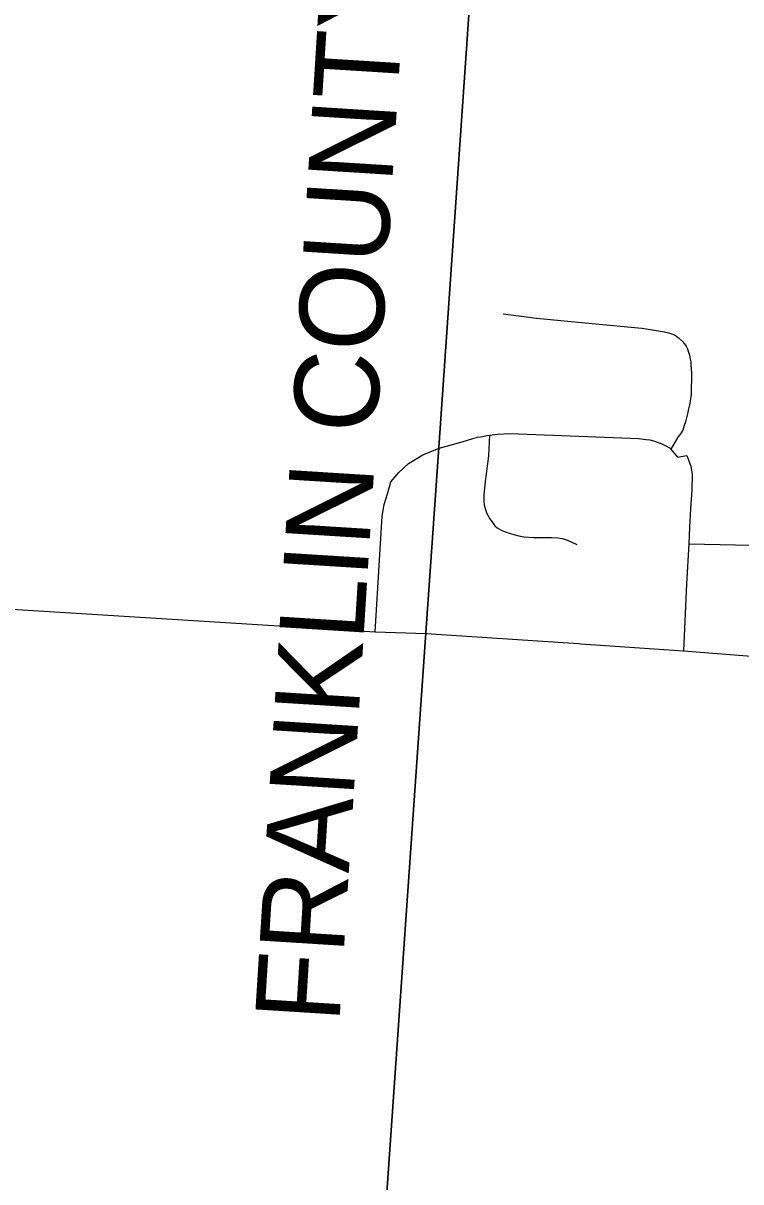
# Model space of a CAD drawing. Extents: x 1880545 to 1948545, y 79309 to 723051.
# Drawn here: x 1887669 to 1890853, y 706837 to 711978 of the extents above; entities that cross this region are included whole.
import ezdxf

# ---------------------------------------------------------------- set-up
doc = ezdxf.new("R2010")
doc.units = 0
for name, color, linetype in [('GM_X_City_Street', 7, 'Continuous'), ('GM_X_County', 7, 'Continuous'), ('GM_X_County_Text', 7, 'Continuous'), ('GM_X_Township', 7, 'Continuous'), ('GM_X_Township_Road', 7, 'Continuous')]:
    doc.layers.add(name, color=color, linetype=linetype)

msp = doc.modelspace()

# ---------------------------------------------------------------- linework, layer by layer
at = {"layer": 'GM_X_City_Street'}
msp.add_line((1890622.3, 709667), (1891097.2, 709657.6), dxfattribs=at)
for points in [[(1889799, 710687.4), (1889946.7, 710668.7), (1890194.3, 710645.5), (1890414, 710624.4), (1890469.9, 710616.2), (1890513.8, 710607.9), (1890533.8, 710603.8), (1890545.8, 710599.8), (1890561.7, 710593.7), (1890577.6, 710581.6), (1890593.6, 710567.4), (1890603.5, 710555.4), (1890611.4, 710545.3), (1890617.3, 710533.3), (1890619.3, 710523.2), (1890625.2, 710505.1), (1890629.1, 710487.1), (1890631.1, 710475.1), (1890631, 710461), (1890634.8, 710426.9), (1890632.4, 710330.6), (1890628.2, 710300.6), (1890626.2, 710284.5), (1890620, 710260.5), (1890618, 710250.5), (1890615.9, 710238.5), (1890607.8, 710208.5), (1890601.7, 710192.4), (1890595.7, 710172.4), (1890585.6, 710156.4), (1890573.5, 710140.4), (1890543, 710088.1)], [(1889514.4, 710091.8), (1889616.4, 710120.7), (1889664.5, 710134.6), (1889684.5, 710140.5), (1889708.5, 710144.4), (1889726.4, 710148.3), (1889739, 710149.8), (1889774.4, 710154.1), (1889828.4, 710157.9), (1890325.8, 710137.6), (1890399.7, 710135.2), (1890433.6, 710131), (1890449.6, 710129), (1890465.5, 710124.9), (1890499.5, 710112.7), (1890517.4, 710104.6), (1890539.3, 710092.4), (1890543, 710088.1), (1890573.1, 710052.2), (1890613.4, 710059.8), (1890631.2, 710012.4), (1890637.1, 709975.3), (1890635.7, 709905.6), (1890629.7, 709824.1), (1890625.3, 709741.1), (1890622.3, 709667), (1890613, 709490.7), (1890599.2, 709192.2)], [(1889739, 710149.8), (1889734, 710058), (1889719.5, 709943.8), (1889713.2, 709883.7), (1889713.1, 709857.6), (1889715, 709839.5), (1889720.9, 709819.4), (1889724.8, 709805.4), (1889732.7, 709791.3), (1889738.7, 709779.3), (1889752.6, 709761.1), (1889762.5, 709747.1), (1889772.4, 709739), (1889782.4, 709733), (1889792.4, 709726.9), (1889826.3, 709714.7), (1889846.2, 709708.6), (1889868.2, 709702.5), (1889890.1, 709698.4), (1889934.1, 709696.2), (1889974, 709696), (1890014, 709695.8), (1890042, 709693.7), (1890061.9, 709691.6), (1890083.9, 709683.4), (1890125.7, 709665.2)], [(1889231.1, 709277.2), (1889262.6, 709790.1), (1889271.2, 709841.6), (1889285.5, 709888.9), (1889300.5, 709943.4), (1889335.6, 709984.6), (1889378.3, 710024.4), (1889442.5, 710062.6), (1889514.4, 710091.8)], [(1885499.9, 709731.5), (1885944.9, 709695.5), (1886695.4, 709651.2), (1886759.9, 709648.3), (1886815.8, 709638.2), (1886880.3, 709611), (1887247, 709423.3), (1887290, 709406.1), (1887357.3, 709394.7), (1889231.1, 709277.2), (1889457.2, 709269.4)]]:
    msp.add_lwpolyline(points, dxfattribs=at)
at = {"layer": 'GM_X_County'}
msp.add_lwpolyline([(1891843, 720211.7), (1891817.3, 719823), (1890199.9, 719967.4), (1890149.5, 719242.8), (1889939.7, 716226.1), (1889896.4, 715603.5), (1889789, 714059.4), (1889788.8, 714056.5), (1889727.7, 713178.3), (1889727.7, 713177.2), (1889679.5, 712484.9), (1889676.5, 712442.3), (1889513.2, 710094.6), (1889456, 709272.2), (1889271.5, 706620), (1886740.8, 706792.8), (1884485.1, 706946.7)], dxfattribs=at)
at = {"layer": 'GM_X_Township'}
for points in [[(1886104.1, 720211.7), (1886445.3, 720189.4), (1890199.9, 719967.4), (1890149.5, 719242.8), (1889939.7, 716226.1), (1889896.4, 715603.5), (1889789, 714059.4), (1889788.8, 714056.5), (1889727.7, 713178.3), (1889727.7, 713177.2), (1889679.5, 712484.9), (1889676.5, 712442.3), (1889513.2, 710094.6), (1889456, 709272.2), (1889271.5, 706620), (1886740.8, 706792.8), (1884485.1, 706946.7)], [(1889271.5, 706620), (1889456, 709272.2), (1889513.2, 710094.6), (1889676.5, 712442.3), (1889679.5, 712484.9), (1889727.7, 713177.2), (1889727.7, 713178.3), (1889788.8, 714056.5), (1889789, 714059.4), (1889896.4, 715603.5), (1889939.7, 716226.1), (1890149.5, 719242.8), (1890199.9, 719967.4), (1891817.3, 719823), (1893081.4, 719771.3), (1893522.1, 719763.2), (1894774.7, 719644.4), (1896793, 719531.9), (1896833.7, 719533.1), (1897456.4, 719506.8), (1898145.1, 719477.4), (1899877.1, 719377.9), (1904377.2, 719098.9)]]:
    msp.add_lwpolyline(points, dxfattribs=at)
at = {"layer": 'GM_X_Township_Road'}
msp.add_line((1889457.2, 709269.4), (1890133, 709225.3), dxfattribs=at)
msp.add_lwpolyline([(1890133, 709225.3), (1890143.4, 709224.6), (1890599.2, 709192.2), (1891013.2, 709160.4)], dxfattribs=at)

# ---------------------------------------------------------------- texts
at = {"layer": 'GM_X_County_Text'}
msp.add_text('FRANKLIN COUNTY', height=375, rotation=86.3996, dxfattribs=at).set_placement((1889071.7, 707537.2))

doc.saveas('drawing.dxf')
